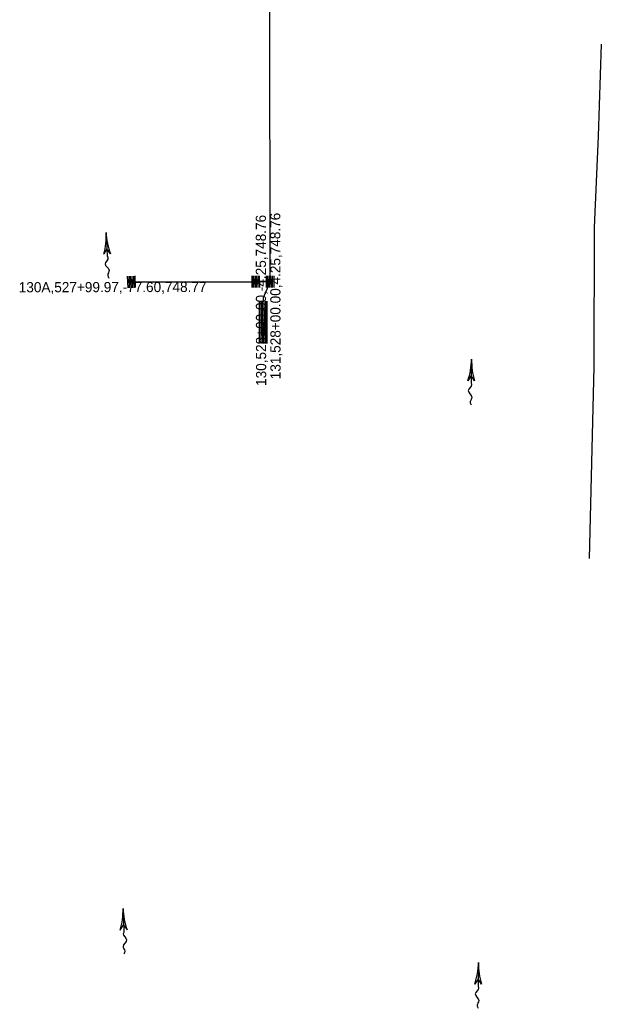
# Model space of a CAD drawing. Extents: x 593481 to 595602, y 151646 to 157396.
# Drawn here: x 594219 to 594562, y 151646 to 152230 of the extents above; entities that cross this region are included whole.
import ezdxf

# ---------------------------------------------------------------- set-up
doc = ezdxf.new("R2010")
doc.units = 0
for name, color, linetype in [('P_ALI_50_Equation', 7, 'Continuous'), ('P_DRN_Flow', 7, 'Continuous'), ('P_DRN_Inlet', 7, 'Continuous'), ('P_DRN_SS_UG', 7, 'Continuous')]:
    doc.layers.add(name, color=color, linetype=linetype)

msp = doc.modelspace()

# ---------------------------------------------------------------- linework, layer by layer
at = {"layer": 'P_DRN_Flow'}
for p, q in [((594269.87, 152104.31), (594270.61, 152090.2)), ((594485.72, 152029.44), (594485.4, 152015.31)), ((594279.89, 151704.97), (594280.28, 151690.84)), ((594489.82, 151673.01), (594489.5, 151658.88))]:
    msp.add_line(p, q, dxfattribs=at)
for points in [[(594272.54, 152091.64), (594270.38, 152094.73), (594268.55, 152091.43)], [(594487.43, 152016.6), (594485.51, 152019.84), (594483.43, 152016.68)], [(594278.24, 151692.12), (594280.15, 151695.37), (594282.24, 151692.23)], [(594491.53, 151660.17), (594489.61, 151663.41), (594487.53, 151660.25)]]:
    msp.add_lwpolyline(points, dxfattribs=at)
for centre, start, end in [((594227.97, 152102.11), 345.24407, 3.00639), ((594311.77, 152106.51), 183.00639, 200.76871), ((594443.77, 152030.38), 340.95171, 358.71403), ((594527.67, 152028.49), 178.71403, 196.47635), ((594237.95, 151703.81), 343.81646, 1.57878), ((594321.83, 151706.12), 181.57878, 199.3411), ((594447.87, 151673.95), 340.95171, 358.71403), ((594531.76, 151672.06), 178.71403, 196.47635)]:
    msp.add_arc(centre, 41.96, start, end, dxfattribs=at)
for points in [[(594270.61, 152090.2), (594270.97, 152089.44), (594269.28, 152085.73), (594271.68, 152081.93), (594270.88, 152079.06), (594271.6, 152077.37)], [(594485.4, 152015.31), (594485.7, 152014.52), (594483.73, 152010.95), (594485.84, 152006.98), (594484.84, 152004.18), (594485.43, 152002.43)], [(594280.28, 151690.84), (594279.99, 151690.05), (594281.97, 151686.49), (594279.88, 151682.51), (594280.9, 151679.71), (594280.32, 151677.97)], [(594489.5, 151658.88), (594489.8, 151658.09), (594487.83, 151654.52), (594489.94, 151650.55), (594488.94, 151647.75), (594489.53, 151646)]]:
    msp.add_spline(points, degree=3, dxfattribs=at)
at = {"layer": 'P_DRN_Inlet'}
for p, q in [((594282.83, 152071.56), (594282.59, 152078.43)), ((594283.73, 152071.59), (594283.49, 152078.46)), ((594284.63, 152071.62), (594284.39, 152078.49)), ((594285.53, 152071.65), (594285.29, 152078.52)), ((594286.43, 152071.68), (594286.19, 152078.55)), ((594287.33, 152071.72), (594287.09, 152078.59)), ((594356.07, 152071.79), (594356.05, 152078.67)), ((594356.97, 152071.8), (594356.95, 152078.67)), ((594357.87, 152071.8), (594357.85, 152078.67)), ((594358.77, 152071.8), (594358.75, 152078.67)), ((594359.67, 152071.8), (594359.65, 152078.68)), ((594360.57, 152071.8), (594360.55, 152078.68)), ((594364.57, 152071.81), (594364.55, 152078.68)), ((594365.47, 152071.81), (594365.45, 152078.69)), ((594366.37, 152071.81), (594366.35, 152078.69)), ((594367.27, 152071.81), (594367.25, 152078.69)), ((594368.17, 152071.82), (594368.15, 152078.69)), ((594369.07, 152071.82), (594369.05, 152078.69)), ((594360.32, 152063.63), (594360.36, 152038.63)), ((594361.22, 152063.63), (594361.26, 152038.63)), ((594362.12, 152063.63), (594362.16, 152038.63)), ((594363.02, 152063.63), (594363.06, 152038.63)), ((594363.92, 152063.63), (594363.96, 152038.63)), ((594364.82, 152063.64), (594364.86, 152038.64))]:
    msp.add_line(p, q, dxfattribs=at)
for points in [[(594285.99, 152074.11), (594285.92, 152076.11), (594283.92, 152076.04), (594283.99, 152074.04)], [(594359.31, 152074.24), (594359.31, 152076.24), (594357.31, 152076.23), (594357.31, 152074.23)], [(594367.81, 152074.25), (594367.81, 152076.25), (594365.81, 152076.25), (594365.81, 152074.25)], [(594361.58, 152058.4), (594361.6, 152043.86), (594363.6, 152043.86), (594363.58, 152058.41)]]:
    msp.add_lwpolyline(points, close=True, dxfattribs=at)
at = {"layer": 'P_DRN_SS_UG'}
for p, q in [((594366.81, 152075.25), (594366.27, 152375.25)), ((594284.96, 152075.07), (594358.31, 152075.24)), ((594358.31, 152075.24), (594366.81, 152075.25))]:
    msp.add_line(p, q, dxfattribs=at)
for points in [[(594562.23, 152215.56), (594560.36, 152161.1), (594558.01, 152107.21), (594557.91, 152024.92), (594555.05, 151911.63)], [(594366.81, 152075.25), (594362.58, 152065.63), (594362.58, 152063.63)]]:
    msp.add_lwpolyline(points, dxfattribs=at)

# ---------------------------------------------------------------- texts
at = {"layer": 'P_ALI_50_Equation'}
for s, rotation, p in [('131,528+00.00,4.25,748.76', 90.10301, (594372.91, 152017.58)), ('130,528+00.00,-4.25,748.76', 90.10301, (594364.42, 152013.64)), ('130A,527+99.97,-77.60,748.77', 0.10301, (594218.31, 152068.95))]:
    msp.add_text(s, height=6, rotation=rotation, dxfattribs=at).set_placement(p)

doc.saveas('drawing.dxf')
